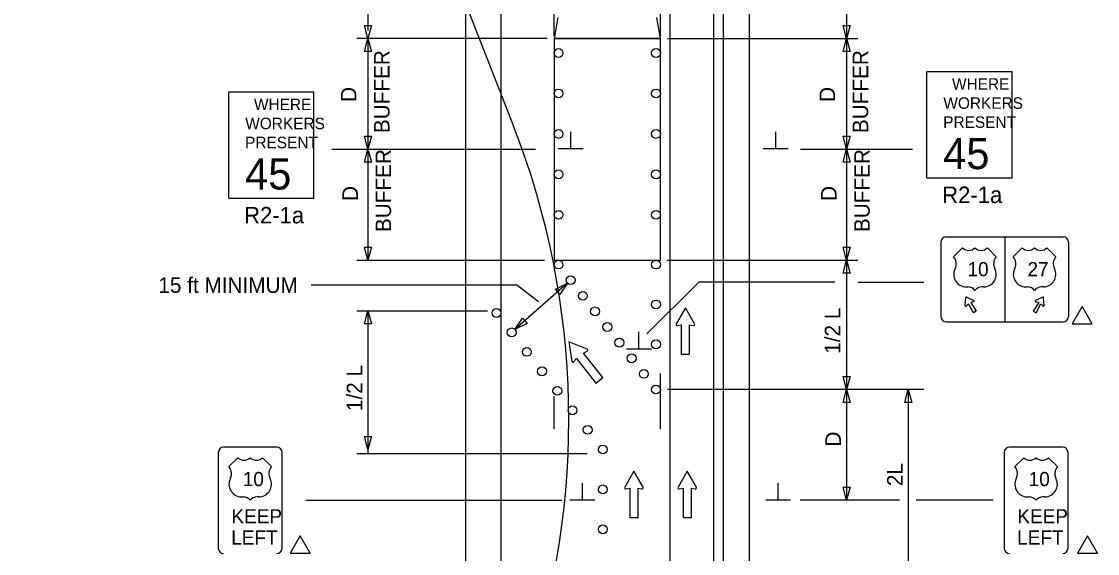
# Model space of a CAD drawing. Extents: x 16486 to 19506, y 5576 to 7023.
# Drawn here: x 16687.6 to 17173.2, y 6261.3 to 6501.5 of the extents above; entities that cross this region are included whole.
import ezdxf

# ---------------------------------------------------------------- set-up
doc = ezdxf.new("R2010")
doc.units = 0
for name, color, linetype in [('ALI_LEGAL_EX', 7, 'Continuous'), ('Level 3', 7, 'Continuous'), ('MT_SCRATCH_LEVEL_A', 7, 'Continuous'), ('MT_SCRATCH_LEVEL_E', 7, 'Continuous'), ('PAVT_EDGE_EX', 7, 'Continuous'), ('TRAFFIC_SIGNS_PR', 7, 'Continuous'), ('TYPICAL_EX', 7, 'Continuous'), ('TYPICAL_TEXT_DIMEN_PR', 7, 'Continuous')]:
    doc.layers.add(name, color=color, linetype=linetype)

msp = doc.modelspace()

# ---------------------------------------------------------------- linework, layer by layer
at = {"layer": 'ALI_LEGAL_EX'}
for p, q in [((16687.64, 7022.55), (16909.67, 6454.18)), ((16980.24, 6998.86), (16980.24, 6180.72)), ((17004.24, 6998.86), (17004.24, 6180.72)), ((16980.24, 6946.95), (16980.24, 6083.04)), ((17004.24, 6946.95), (17004.24, 6083.04))]:
    msp.add_line(p, q, dxfattribs=at)
for points in [[(16927.96, 6495.08), (16927.96, 6520.08)], [(16975.96, 6495.08), (16975.96, 6520.08)], [(16975.96, 6317.56), (16975.96, 6342.56)], [(16927.96, 6317.56), (16927.96, 6332.2)]]:
    msp.add_lwpolyline(points, dxfattribs=at)
msp.add_arc((16570.62, 6321.73), 364, 341.1474, 21.3382, dxfattribs=at)
at = {"layer": 'Level 3'}
msp.add_line((16843.96, 6505.27), (16843.96, 6497.36), dxfattribs=at)
at = {"layer": 'MT_SCRATCH_LEVEL_A'}
msp.add_lwpolyline([(16929.62, 6503.3), (16927.96, 6493.83), (16975.96, 6493.83), (16974.3, 6503.3)], dxfattribs=at)
at = {"layer": 'MT_SCRATCH_LEVEL_E'}
for p, q in [((16987.21, 6372.18), (16983.1, 6364.94)), ((16991.36, 6364.94), (16987.21, 6372.18)), ((16983.58, 6364.26), (16985.36, 6364.58)), ((16985.36, 6364.58), (16985.36, 6351.32)), ((16989.1, 6351.32), (16989.1, 6364.58)), ((16989.1, 6364.58), (16990.88, 6364.26)), ((16985.36, 6351.32), (16989.1, 6351.32)), ((16963.96, 6298.46), (16959.85, 6291.22)), ((16968.11, 6291.22), (16963.96, 6298.46)), ((16988.02, 6298.46), (16983.9, 6291.22)), ((16992.16, 6291.22), (16988.02, 6298.46)), ((16960.33, 6290.53), (16962.11, 6290.85)), ((16962.11, 6290.85), (16962.11, 6277.59)), ((16965.85, 6277.59), (16965.85, 6290.85)), ((16965.85, 6290.85), (16967.63, 6290.53)), ((16984.39, 6290.53), (16986.16, 6290.85)), ((16986.16, 6290.85), (16986.16, 6277.59)), ((16989.91, 6277.59), (16989.91, 6290.85)), ((16989.91, 6290.85), (16991.68, 6290.53)), ((16962.11, 6277.59), (16965.85, 6277.59)), ((16986.16, 6277.59), (16989.91, 6277.59))]:
    msp.add_line(p, q, dxfattribs=at)
for centre, start, end in [((16983.51, 6364.72), 150.4248, 279.9638), ((16990.95, 6364.72), 260.0362, 29.7731), ((16960.26, 6290.99), 150.4248, 279.9638), ((16967.7, 6290.99), 260.0362, 29.7731), ((16984.31, 6290.99), 150.4248, 279.9638), ((16991.75, 6290.99), 260.0362, 29.7731)]:
    msp.add_arc(centre, 0.463, start, end, dxfattribs=at)
at = {"layer": 'PAVT_EDGE_EX'}
for p, q in [((16887.96, 6505.27), (16887.96, 6073.13)), ((16903.96, 6505.27), (16903.96, 6073.13)), ((16999.96, 6505.27), (16999.96, 6073.13)), ((17015.96, 6505.27), (17015.96, 6073.13))]:
    msp.add_line(p, q, dxfattribs=at)
msp.add_lwpolyline([(16975.96, 6493.83), (16927.96, 6493.83), (16927.96, 6393.76), (16975.96, 6393.76)], close=True, dxfattribs=at)
at = {"layer": 'TRAFFIC_SIGNS_PR'}
for p, q in [((17096.23, 6478.98), (17134.63, 6478.98)), ((17096.23, 6430.98), (17096.23, 6478.98)), ((17134.63, 6430.98), (17134.63, 6478.98)), ((16781.21, 6469.79), (16819.61, 6469.79)), ((16781.21, 6421.79), (16781.21, 6469.79)), ((16819.61, 6421.79), (16819.61, 6469.79)), ((17096.23, 6430.98), (17134.63, 6430.98)), ((16781.21, 6421.79), (16819.61, 6421.79)), ((17104.92, 6404.3), (17157.72, 6404.3)), ((17131.32, 6404.3), (17131.32, 6365.9)), ((17102.52, 6401.9), (17102.52, 6368.3)), ((17160.12, 6401.9), (17160.12, 6368.3)), ((17113.49, 6373.25), (17113.78, 6376.87)), ((17114.15, 6377.09), (17117.43, 6375.52)), ((17148.48, 6377.09), (17145.2, 6375.52)), ((17149.14, 6373.25), (17148.85, 6376.87)), ((17104.92, 6365.9), (17157.72, 6365.9)), ((16802.83, 6309.34), (16778.83, 6309.34)), ((17157.47, 6309.34), (17133.47, 6309.34)), ((16776.43, 6306.94), (16776.43, 6263.74)), ((16805.23, 6263.74), (16805.23, 6306.94)), ((17131.07, 6306.94), (17131.07, 6263.74)), ((17159.87, 6263.74), (17159.87, 6306.94))]:
    msp.add_line(p, q, dxfattribs=at)
for points in [[(17117.39, 6375.04), (17115.98, 6374.65), (17118.49, 6370.67), (17117.16, 6369.9), (17114.98, 6374.07), (17113.94, 6373.04)], [(17145.24, 6375.04), (17146.65, 6374.65), (17144.14, 6370.67), (17145.47, 6369.9), (17147.66, 6374.07), (17148.7, 6373.04)]]:
    msp.add_lwpolyline(points, dxfattribs=at)
for centre in [(16929.97, 6487.27), (16973.96, 6487.27), (16929.97, 6469.01), (16973.96, 6469.01), (16929.97, 6450.74), (16973.96, 6450.74), (16929.97, 6432.48), (16973.96, 6432.48), (16929.97, 6414.21), (16973.96, 6414.21), (16929.97, 6391.76), (16929.97, 6391.76), (16973.96, 6391.76), (16935.46, 6384.71), (16940.96, 6377.66), (16973.96, 6373.76), (16901.96, 6369.92), (16946.45, 6370.61), (16951.95, 6363.56), (16908.82, 6361.13), (16957.44, 6356.51), (16973.96, 6355.76), (16915.68, 6352.34), (16962.94, 6349.47), (16922.53, 6343.54), (16968.44, 6342.42), (16929.39, 6334.75), (16973.93, 6335.37), (16936.25, 6325.95), (16943.1, 6317.16), (16949.96, 6308.31), (16949.96, 6290.26), (16949.96, 6272.26)]:
    msp.add_circle(centre, 2, dxfattribs=at)
for centre, radius, start, end in [((17104.91, 6401.9), 2.4, 90, 180), ((17104.91, 6401.9), 2.4, 90, 180), ((17157.71, 6401.9), 2.4, 0, 90), ((17114.04, 6376.85), 0.26, 64.4823, 175.5177), ((17117.31, 6375.29), 0.26, 285.9885, 64.4823), ((17145.31, 6375.29), 0.26, 115.5177, 254.0115), ((17148.59, 6376.85), 0.26, 4.4823, 115.5177), ((17113.75, 6373.23), 0.26, 175.5177, 314.0115), ((17148.88, 6373.23), 0.26, 225.9885, 4.4823), ((17104.91, 6368.3), 2.4, 180, 270), ((17157.71, 6368.3), 2.4, 270, 0), ((16778.83, 6306.94), 2.4, 90, 180), ((16802.83, 6306.94), 2.4, 0, 90), ((17133.47, 6306.94), 2.4, 90, 180), ((17157.47, 6306.94), 2.4, 0, 90), ((16778.83, 6263.74), 2.4, 180, 270), ((16802.83, 6263.74), 2.4, 270, 0), ((17133.47, 6263.74), 2.4, 180, 270), ((17157.47, 6263.74), 2.4, 270, 0)]:
    msp.add_arc(centre, radius, start, end, dxfattribs=at)
at = {"layer": 'TYPICAL_EX'}
for p, q in [((17108.27, 6395.3), (17112.27, 6399.3)), ((17127.47, 6395.3), (17123.47, 6399.3)), ((17135.16, 6395.3), (17139.16, 6399.3)), ((17154.37, 6395.3), (17150.36, 6399.3)), ((17113.86, 6381.69), (17114.66, 6381.69)), ((17121.87, 6381.69), (17121.07, 6381.69)), ((17140.76, 6381.69), (17141.56, 6381.69)), ((17148.77, 6381.69), (17147.97, 6381.69)), ((16781.23, 6300.54), (16785.23, 6304.54)), ((16800.43, 6300.54), (16796.43, 6304.54)), ((17135.87, 6300.54), (17139.87, 6304.54)), ((17155.07, 6300.54), (17151.07, 6304.54)), ((16786.82, 6286.93), (16787.62, 6286.93)), ((16794.83, 6286.93), (16794.03, 6286.93)), ((17141.47, 6286.93), (17142.27, 6286.93)), ((17149.48, 6286.93), (17148.68, 6286.93))]:
    msp.add_line(p, q, dxfattribs=at)
for centre, radius, start, end in [((17115.07, 6402.22), 4.04, 226.1404, 313.8596), ((17120.66, 6402.22), 4.04, 226.1404, 313.8596), ((17141.96, 6402.22), 4.04, 226.1404, 313.8596), ((17147.56, 6402.22), 4.04, 226.1404, 313.8596), ((17104.47, 6392.1), 4.96, 333.0977, 40.1936), ((17131.26, 6392.1), 4.96, 139.8064, 206.9023), ((17131.37, 6392.1), 4.96, 333.0977, 40.1936), ((17158.16, 6392.1), 4.96, 139.8064, 206.9023), ((17113.87, 6387.29), 5.59, 152.6698, 269.9013), ((17121.86, 6387.29), 5.59, 270.0987, 27.3302), ((17140.77, 6387.29), 5.59, 152.6698, 269.9013), ((17148.76, 6387.29), 5.59, 270.0987, 27.3302), ((17114.67, 6377.68), 4.01, 37.1038, 90.1385), ((17121.06, 6377.68), 4.01, 89.8615, 142.8962), ((17141.57, 6377.68), 4.01, 37.1038, 90.1385), ((17147.96, 6377.68), 4.01, 89.8615, 142.8962), ((16788.03, 6307.45), 4.04, 226.1404, 313.8596), ((16793.63, 6307.45), 4.04, 226.1404, 313.8596), ((17142.67, 6307.45), 4.04, 226.1404, 313.8596), ((17148.27, 6307.45), 4.04, 226.1404, 313.8596), ((16777.44, 6297.33), 4.96, 333.0977, 40.1936), ((16804.22, 6297.33), 4.96, 139.8064, 206.9023), ((17132.08, 6297.33), 4.96, 333.0977, 40.1936), ((17158.86, 6297.33), 4.96, 139.8064, 206.9023), ((16786.83, 6292.52), 5.59, 152.6698, 269.9013), ((16794.82, 6292.52), 5.59, 270.0987, 27.3302), ((17141.48, 6292.52), 5.59, 152.6698, 269.9013), ((17149.47, 6292.52), 5.59, 270.0987, 27.3302), ((16787.63, 6282.92), 4.01, 37.1038, 90.1385), ((16794.02, 6282.92), 4.01, 89.8615, 142.8962), ((17142.28, 6282.92), 4.01, 37.1038, 90.1385), ((17148.67, 6282.92), 4.01, 89.8615, 142.8962)]:
    msp.add_arc(centre, radius, start, end, dxfattribs=at)
at = {"layer": 'TYPICAL_TEXT_DIMEN_PR'}
for p, q in [((17059.96, 6505.27), (17059.96, 6493.83)), ((16843.96, 6493.83), (16842.39, 6499.69)), ((16842.39, 6499.69), (16843.96, 6499.69)), ((16843.96, 6499.69), (16845.53, 6499.69)), ((16845.53, 6499.69), (16843.96, 6493.83)), ((17059.96, 6493.83), (17058.39, 6499.69)), ((17058.39, 6499.69), (17059.96, 6499.69)), ((17059.96, 6499.69), (17061.53, 6499.69)), ((17061.53, 6499.69), (17059.96, 6493.83)), ((16924.83, 6493.83), (16838.96, 6493.83)), ((16842.39, 6487.96), (16843.96, 6493.83)), ((16843.96, 6493.83), (16845.53, 6487.96)), ((16843.96, 6493.83), (16843.96, 6443.83)), ((16979.16, 6493.83), (17064.96, 6493.83)), ((16979.16, 6493.83), (17064.96, 6493.83)), ((17058.39, 6487.96), (17059.96, 6493.83)), ((17059.96, 6493.83), (17061.53, 6487.96)), ((17059.96, 6493.83), (17059.96, 6443.83)), ((16843.96, 6487.96), (16842.39, 6487.96)), ((16845.53, 6487.96), (16843.96, 6487.96)), ((17059.96, 6487.96), (17058.39, 6487.96)), ((17061.53, 6487.96), (17059.96, 6487.96)), ((16843.96, 6443.83), (16842.39, 6449.69)), ((16842.39, 6449.69), (16843.96, 6449.69)), ((16843.96, 6449.69), (16845.53, 6449.69)), ((16845.53, 6449.69), (16843.96, 6443.83)), ((16935.47, 6443.95), (16935.47, 6451.74)), ((17028, 6443.95), (17028, 6451.74)), ((17059.96, 6443.83), (17058.39, 6449.69)), ((17058.39, 6449.69), (17059.96, 6449.69)), ((17059.96, 6449.69), (17061.53, 6449.69)), ((17061.53, 6449.69), (17059.96, 6443.83)), ((16827.65, 6443.83), (16919.62, 6443.83)), ((16842.39, 6437.96), (16843.96, 6443.83)), ((16843.96, 6443.83), (16845.53, 6437.96)), ((16843.96, 6443.83), (16843.96, 6393.76)), ((16941.09, 6443.95), (16929.84, 6443.95)), ((17033.62, 6443.95), (17022.37, 6443.95)), ((17039.19, 6443.83), (17089.66, 6443.83)), ((17058.39, 6437.96), (17059.96, 6443.83)), ((17059.96, 6443.83), (17061.53, 6437.96)), ((17059.96, 6443.83), (17059.96, 6393.76)), ((16843.96, 6437.96), (16842.39, 6437.96)), ((16845.53, 6437.96), (16843.96, 6437.96)), ((17059.96, 6437.96), (17058.39, 6437.96)), ((17061.53, 6437.96), (17059.96, 6437.96)), ((16843.96, 6427.76), (16843.96, 6416.31)), ((17059.96, 6427.76), (17059.96, 6416.31)), ((16843.96, 6416.31), (16843.96, 6393.76)), ((17059.96, 6416.31), (17059.96, 6393.76)), ((16843.96, 6393.76), (16842.39, 6399.62)), ((16842.39, 6399.62), (16843.96, 6399.62)), ((16843.96, 6393.76), (16842.39, 6399.62)), ((16842.39, 6399.62), (16843.96, 6399.62)), ((16843.96, 6399.62), (16845.53, 6399.62)), ((16845.53, 6399.62), (16843.96, 6393.76)), ((16843.96, 6399.62), (16845.53, 6399.62)), ((16845.53, 6399.62), (16843.96, 6393.76)), ((17059.96, 6393.76), (17058.39, 6399.62)), ((17058.39, 6399.62), (17059.96, 6399.62)), ((17059.96, 6393.76), (17058.39, 6399.62)), ((17058.39, 6399.62), (17059.96, 6399.62)), ((17059.96, 6399.62), (17061.53, 6399.62)), ((17061.53, 6399.62), (17059.96, 6393.76)), ((17059.96, 6399.62), (17061.53, 6399.62)), ((17061.53, 6399.62), (17059.96, 6393.76)), ((16838.96, 6393.76), (16923.6, 6393.76)), ((16978.87, 6393.76), (17064.96, 6393.76)), ((16979.16, 6393.76), (17064.96, 6393.76)), ((17058.39, 6387.9), (17059.96, 6393.76)), ((17059.96, 6393.76), (17059.96, 6335.37)), ((17059.96, 6393.76), (17061.53, 6387.9)), ((17059.96, 6387.9), (17058.39, 6387.9)), ((17061.53, 6387.9), (17059.96, 6387.9)), ((16818.4, 6382.68), (16911.01, 6382.68)), ((16933.97, 6383.38), (16910.32, 6362.46)), ((16920.87, 6374.88), (16911.01, 6382.68)), ((16928.54, 6380.68), (16933.97, 6383.38)), ((16929.58, 6379.5), (16928.54, 6380.68)), ((16933.97, 6383.38), (16930.62, 6378.32)), ((16969.8, 6360.43), (16993.21, 6383.75)), ((17054.66, 6383.75), (16993.21, 6383.75)), ((17065.19, 6383.75), (17094.75, 6383.75)), ((16930.62, 6378.32), (16929.58, 6379.5)), ((16838.96, 6370.82), (16897.86, 6370.82)), ((16842.39, 6364.96), (16843.96, 6370.82)), ((16843.96, 6370.82), (16843.96, 6306.31)), ((16843.96, 6370.82), (16845.53, 6364.96)), ((16910.32, 6362.46), (16913.67, 6367.52)), ((16913.67, 6367.52), (16914.71, 6366.34)), ((16914.71, 6366.34), (16915.75, 6365.16)), ((16843.96, 6364.96), (16842.39, 6364.96)), ((16845.53, 6364.96), (16843.96, 6364.96)), ((16915.75, 6365.16), (16910.32, 6362.46)), ((16966.24, 6353.64), (16966.24, 6361.42)), ((16942.84, 6353.63), (16934.57, 6356.93)), ((16934.57, 6356.93), (16935.94, 6348.16)), ((16941.2, 6351.82), (16942.89, 6352.74)), ((16949.98, 6340.75), (16941.2, 6351.82)), ((16971.86, 6353.64), (16960.61, 6353.64)), ((16936.79, 6347.9), (16938.07, 6349.34)), ((16938.07, 6349.34), (16946.86, 6338.27)), ((17059.96, 6335.37), (17058.39, 6341.23)), ((17058.39, 6341.23), (17059.96, 6341.23)), ((17059.96, 6341.23), (17061.53, 6341.23)), ((17061.53, 6341.23), (17059.96, 6335.37)), ((16946.86, 6338.27), (16949.98, 6340.75)), ((17094.75, 6335.37), (16979.16, 6335.37)), ((17058.39, 6329.51), (17059.96, 6335.37)), ((17059.96, 6335.37), (17061.53, 6329.51)), ((17059.96, 6335.37), (17059.96, 6285.37)), ((17086.2, 6329.51), (17087.77, 6335.37)), ((17087.77, 6335.37), (17087.77, 6254.26)), ((17087.77, 6335.37), (17089.34, 6329.51)), ((17059.96, 6329.51), (17058.39, 6329.51)), ((17061.53, 6329.51), (17059.96, 6329.51)), ((17087.77, 6329.51), (17086.2, 6329.51)), ((17089.34, 6329.51), (17087.77, 6329.51)), ((16843.96, 6308.31), (16842.39, 6314.17)), ((16842.39, 6314.17), (16843.96, 6314.17)), ((16843.96, 6314.17), (16845.53, 6314.17)), ((16845.53, 6314.17), (16843.96, 6308.31)), ((16942.85, 6306.31), (16838.96, 6306.31)), ((16940.71, 6285.37), (16940.71, 6293.15)), ((17029.09, 6285.37), (17029.09, 6293.15)), ((17059.96, 6285.37), (17058.39, 6291.23)), ((17058.39, 6291.23), (17059.96, 6291.23)), ((17059.96, 6291.23), (17061.53, 6291.23)), ((17061.53, 6291.23), (17059.96, 6285.37)), ((16815.99, 6285.37), (16931.47, 6285.37)), ((16946.34, 6285.37), (16935.09, 6285.37)), ((17034.71, 6285.37), (17023.46, 6285.37)), ((17083.77, 6285.37), (17038.96, 6285.37)), ((17126.1, 6285.37), (17091.4, 6285.37))]:
    msp.add_line(p, q, dxfattribs=at)
for points in [[(17166.23, 6372.88), (17161.71, 6365.05), (17170.76, 6365.05)], [(16813.32, 6269.3), (16808.8, 6261.46), (16817.85, 6261.46)], [(17168.64, 6269.3), (17164.12, 6261.46), (17173.17, 6261.46)]]:
    msp.add_lwpolyline(points, close=True, dxfattribs=at)
for centre, start, end in [((16942.64, 6353.17), 298.4553, 68.1923), ((16936.43, 6348.24), 188.844, 318.3829)]:
    msp.add_arc(centre, 0.494, start, end, dxfattribs=at)

# ---------------------------------------------------------------- texts
at = {"layer": 'TRAFFIC_SIGNS_PR'}
for s, height, p in [('WHERE', 5.2, (17107.54, 6470.67)), ('WORKERS', 5.2, (17103.62, 6462.07)), ('WHERE', 5.2, (16792.52, 6461.47)), ('WORKERS', 5.2, (16788.6, 6452.87)), ('PRESENT', 5.2, (17103.55, 6453.47)), ('PRESENT', 5.2, (16788.53, 6444.27)), ('45', 14.031, (17103.54, 6434.84)), ('45', 14.031, (16788.52, 6425.64)), ('R2-1a', 7.44, (17103.09, 6419.54)), ('R2-1a', 7.44, (16788.07, 6410.35)), ('10', 6.4, (17114.52, 6386.5)), ('27', 6.4, (17141.59, 6386.5)), ('10', 6.4, (16787.49, 6291.74)), ('10', 6.4, (17142.13, 6291.74)), ('KEEP', 6.4, (16782.37, 6274.94)), ('KEEP', 6.4, (17137.01, 6274.94)), ('LEFT', 6.4, (16782.28, 6265.34)), ('LEFT', 6.4, (17136.92, 6265.34))]:
    msp.add_text(s, height=height, dxfattribs=at).set_placement(p)
at = {"layer": 'TYPICAL_TEXT_DIMEN_PR'}
for s, rotation, p in [('BUFFER', 89.9795, (16853.7, 6451.09)), ('BUFFER', 89.9795, (17069.7, 6451.09)), ('D', 89.8868, (16838.73, 6465.16)), ('D', 89.8868, (17054.73, 6465.16)), ('BUFFER', 89.9795, (16854.4, 6406.42)), ('BUFFER', 89.9795, (17070.4, 6406.42)), ('D', 89.8868, (16839.43, 6420.48)), ('D', 89.8868, (17055.43, 6420.48)), ('1/2 L', 90, (17057.1, 6351.5)), ('1/2 L', 90, (16841.4, 6325.61)), ('D', 90, (17057.4, 6309.59)), ('2L', 90, (17085.21, 6291.76))]:
    msp.add_text(s, height=7, rotation=rotation, dxfattribs=at).set_placement(p)
msp.add_text('15 ft MINIMUM', height=7, dxfattribs=at).set_placement((16749.39, 6378.98))

doc.saveas('drawing.dxf')
